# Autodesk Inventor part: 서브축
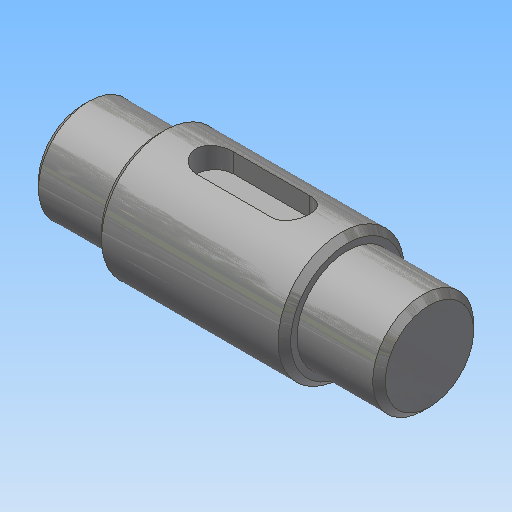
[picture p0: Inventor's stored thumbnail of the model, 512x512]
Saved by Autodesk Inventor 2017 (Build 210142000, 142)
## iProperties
Created: 2019-03
Part Number: 서브축
Material: 강철, 연강
Document SubType Name: Modeling
Designer: mduedu
Density: 1 g/cm^3
Appearance: 강철
Author: mduedu
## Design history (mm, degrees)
sketch "스케치1"
  geometry: L1 (0, 0)-(12, 0); L2 (12, 0)-(12, 8); L3 (12, 8)-(0, 8); L4 (0, 8)-(0, 0); L5 (12, 0)-(42, 0); L6 (42, 0)-(42, 10); L7 (42, 10)-(12, 10); L8 (12, 10)-(12, 0); L9 (42, 0)-(55, 0); L10 (55, 0)-(55, 8); L11 (55, 8)-(42, 8); L12 (42, 8)-(42, 0)
  constraints: 24 end point, 6 parallel, 3 horizontal, 3 perpendicular
  dimensions: "d0" = 16 diameter of L3 L1; "d2" = 20 diameter of L7 L5; "d3" = 16 diameter of L11 L9; "d4" = 12 distance of L2.end L3.end; "d5" = 30 distance of L6.end L7.end; "d6" = 55 distance between parallel lines of L10 L4
revolve "회전1" sketch "스케치1" stored, may be unused: angle "d7" = 90 deg
node "작업 평면1"
sketch "스케치2" dims "d10" = 18
  geometry: L1 (6, -3)-(-6, -3); L2 (-6, -3)-(-6, 3); L3 (-6, 3)-(6, 3); L4 (6, 3)-(6, -3); L5 (15, 10)-(15, -10) reference; 3 further points
  constraints: 8 end point, 2 midpoint, 2 parallel, 2 vertical alignment, 1 horizontal, 1 horizontal alignment, 1 perpendicular, 4 other
  dimensions: "d8" = 6 distance between parallel lines of L3 L1; "d11" = 6 dimension on L5
extrude "돌출1" cut sketch "스케치2" distance "d12" = 3.5; taper "d13" = 0 deg
chamfer "모따기1" distance "d14" = 1; stored, may be unused: second distance "d15" = 2, angle "d16" = 45 deg
chamfer "모따기2" distance "d17" = 1; stored, may be unused: second distance "d18" = 2, angle "d19" = 45 deg
node "솔리드1"
